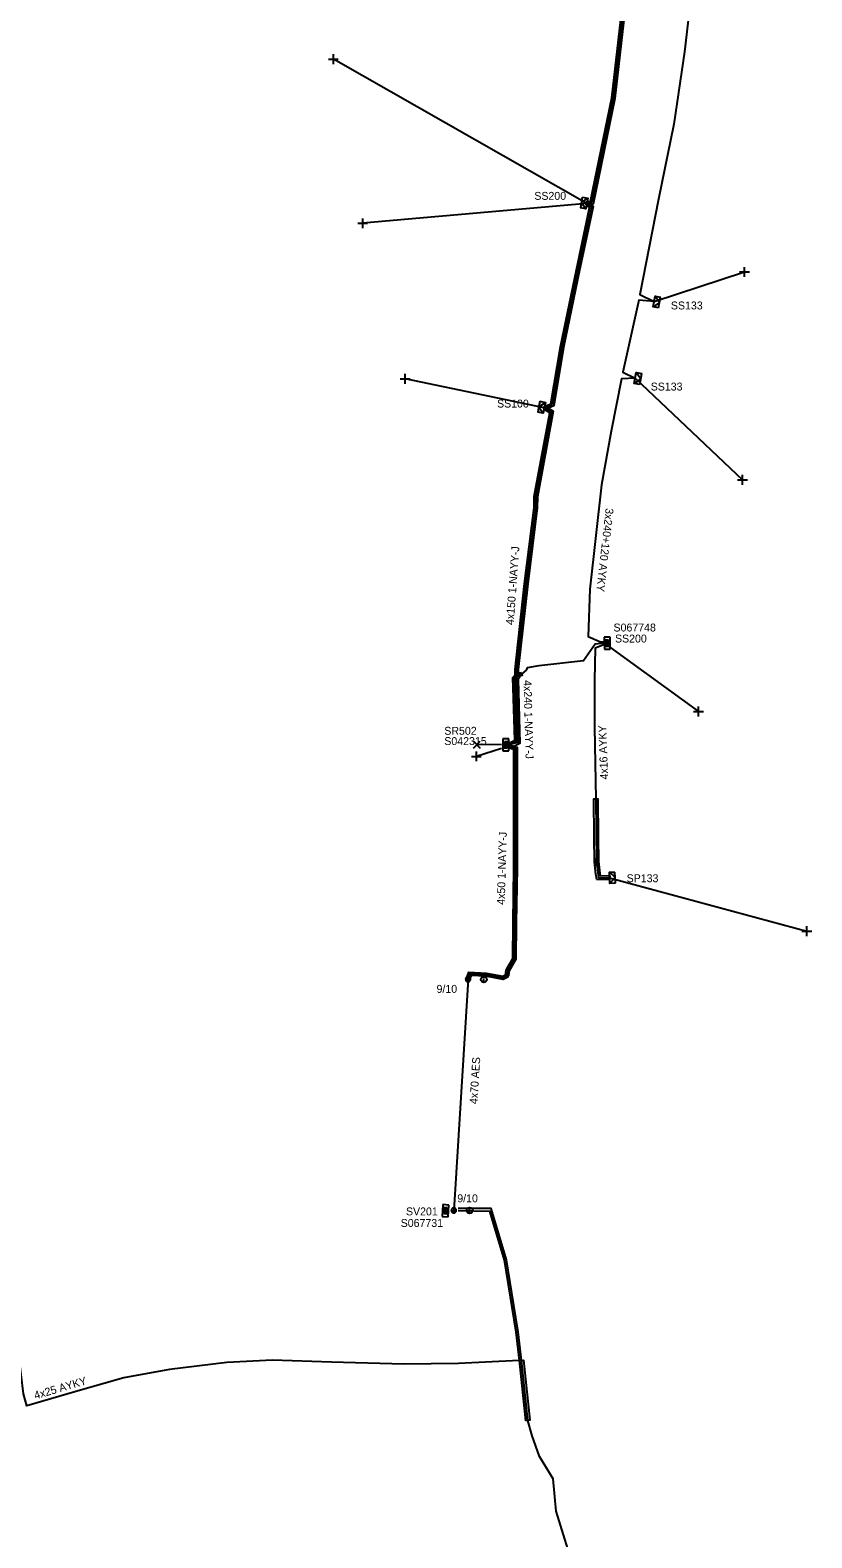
# Model space of a CAD drawing. Extents: x -748492 to -735633, y -1146251 to -1139940.
# Drawn here: x -736089.4 to -735990.6, y -1145586.5 to -1145396.1 of the extents above; entities that cross this region are included whole.
import ezdxf

# ---------------------------------------------------------------- set-up
doc = ezdxf.new("R2010")
doc.units = 0
for name, color, linetype in [('Vrstva 1', 7, 'Continuous'), ('Vrstva 10', 7, 'Continuous'), ('Vrstva 12', 7, 'Continuous'), ('Vrstva 13', 7, 'Continuous'), ('Vrstva 19', 7, 'Continuous'), ('Vrstva 2', 7, 'Continuous'), ('Vrstva 20', 7, 'Continuous'), ('Vrstva 28', 7, 'Continuous'), ('Vrstva 29', 7, 'Continuous'), ('Vrstva 30', 7, 'Continuous'), ('Vrstva 31', 7, 'Continuous'), ('Vrstva 33', 7, 'Continuous'), ('Vrstva 34', 7, 'Continuous'), ('Vrstva 36', 7, 'Continuous'), ('Vrstva 4', 7, 'Continuous'), ('Vrstva 5', 7, 'Continuous'), ('Vrstva 50', 7, 'Continuous'), ('Vrstva 51', 7, 'Continuous'), ('Vrstva 52', 7, 'Continuous'), ('Vrstva 54', 7, 'Continuous'), ('Vrstva 59', 7, 'Continuous'), ('Vrstva 6', 7, 'Continuous'), ('Vrstva 8', 7, 'Continuous'), ('Vrstva 9', 7, 'Continuous')]:
    doc.layers.add(name, color=color, linetype=linetype)

# ---------------------------------------------------------------- blocks, each defined once
blk = doc.blocks.new('NN440')
at = {"layer": 'Vrstva 2'}
for points in [[(0.63, 0), (0.63, 0.06), (0.62, 0.13), (0.6, 0.19), (0.58, 0.25), (0.55, 0.31), (0.51, 0.37), (0.47, 0.42), (0.42, 0.46), (0.37, 0.51), (0.32, 0.54), (0.26, 0.57), (0.2, 0.59), (0.13, 0.61), (0.07, 0.62), (0, 0.63), (-0.06, 0.62), (-0.13, 0.61), (-0.19, 0.59), (-0.26, 0.57), (-0.31, 0.54), (-0.37, 0.51), (-0.42, 0.46), (-0.47, 0.42), (-0.51, 0.37), (-0.54, 0.31), (-0.57, 0.25), (-0.6, 0.19), (-0.62, 0.13), (-0.63, 0.06), (-0.63, 0), (-0.63, -0.07), (-0.62, -0.14), (-0.6, -0.2), (-0.57, -0.26), (-0.54, -0.32), (-0.51, -0.37), (-0.47, -0.43), (-0.42, -0.47), (-0.37, -0.51), (-0.31, -0.55), (-0.26, -0.58), (-0.19, -0.6), (-0.13, -0.62), (-0.06, -0.63), (0, -0.63), (0.07, -0.63), (0.13, -0.62), (0.2, -0.6), (0.26, -0.58), (0.32, -0.55), (0.37, -0.51), (0.42, -0.47), (0.47, -0.43), (0.51, -0.37), (0.55, -0.32), (0.58, -0.26), (0.6, -0.2), (0.62, -0.14), (0.63, -0.07), (0.63, 0)], [(-0.63, 0), (0.63, 0)], [(-0.6, -0.18), (0.57, -0.18)], [(-0.51, -0.32), (0.5, -0.32)], [(-0.37, -0.47), (0.35, -0.47)]]:
    blk.add_lwpolyline(points, dxfattribs=at)
blk = doc.blocks.new('NN770')
at = {"layer": 'Vrstva 10'}
for p, q in [((0, 0.19), (0, 0.26)), ((0, -0.28), (0, 0.11))]:
    blk.add_line(p, q, dxfattribs=at)
blk.add_circle((0, -0.01), 0.375, dxfattribs=at)
blk = doc.blocks.new('NN870')
at = {"layer": 'Vrstva 4'}
for points in [[(0, -0.25), (0.5, 0), (0, 0.25), (-0.5, 0), (0, -0.25)], [(0.37, 0), (0, 0.19), (-0.36, 0), (0, -0.19), (0.37, 0)], [(0.24, 0), (0, 0.12), (-0.25, 0), (0, -0.12), (0.24, 0)], [(0.12, 0), (0, 0.06), (-0.13, 0), (0, -0.06), (0.12, 0)]]:
    blk.add_lwpolyline(points, dxfattribs=at)
blk = doc.blocks.new('NN800')
at = {"layer": 'Vrstva 1'}
for points in [[(-0.44, 0.44), (0.44, -0.44)], [(-0.44, -0.44), (0.44, 0.44)]]:
    blk.add_lwpolyline(points, dxfattribs=at)
blk = doc.blocks.new('NN620')
at = {"layer": 'Vrstva 8'}
for points in [[(0.75, 0), (-0.75, 0)], [(-0.75, 0), (-0.75, -0.75)], [(0.75, -0.75), (0.75, 0)], [(-0.75, -0.75), (0.75, -0.75)], [(0.37, -0.18), (-0.38, -0.18)], [(-0.38, -0.18), (-0.38, -0.56)], [(-0.38, -0.56), (0.37, -0.56)], [(0.32, -0.23), (-0.33, -0.23)], [(-0.33, -0.23), (-0.33, -0.51)], [(-0.33, -0.51), (0.32, -0.51)], [(0.27, -0.27), (-0.28, -0.27)], [(-0.28, -0.27), (-0.28, -0.46)], [(-0.28, -0.46), (0.27, -0.46)], [(0.23, -0.32), (-0.23, -0.32)], [(-0.23, -0.32), (-0.23, -0.42)], [(-0.23, -0.42), (0.23, -0.42)], [(-0.19, -0.37), (0.19, -0.37)], [(0.23, -0.42), (0.23, -0.32)], [(0.27, -0.46), (0.27, -0.27)], [(0.32, -0.51), (0.32, -0.23)], [(0.37, -0.56), (0.37, -0.18)]]:
    blk.add_lwpolyline(points, dxfattribs=at)
blk = doc.blocks.new('NN630')
at = {"layer": 'Vrstva 9'}
for points in [[(0, -0.7), (-0.7, 0)], [(-0.7, -0.7), (-0.7, 0), (0.7, 0), (0.7, -0.7)], [(-0.7, -0.7), (0.7, -0.7)], [(0, -0.7), (0.7, 0)]]:
    blk.add_lwpolyline(points, dxfattribs=at)

msp = doc.modelspace()

# ---------------------------------------------------------------- linework, layer by layer
at = {"layer": 'Vrstva 20'}
for points in [[(-736015.09, -1145385.83), (-736014.27, -1145386.45), (-736014.23, -1145393.69), (-736015.51, -1145404.72), (-736018.26, -1145418.06), (-736019.02, -1145418.18), (-736019.08, -1145417.78), (-736018.6, -1145417.7), (-736015.91, -1145404.66), (-736014.63, -1145393.67), (-736014.67, -1145386.65), (-736015.33, -1145386.15)], [(-736018.92, -1145417.82), (-736018.25, -1145418.37), (-736019.96, -1145426.42), (-736021.98, -1145436.18), (-736023.23, -1145443.55), (-736024.3, -1145443.98), (-736024.44, -1145443.6), (-736023.59, -1145443.27), (-736022.38, -1145436.1), (-736020.36, -1145426.34), (-736018.69, -1145418.53), (-736019.18, -1145418.13)], [(-736024.26, -1145443.62), (-736023.3, -1145444.22), (-736025.28, -1145455.03), (-736025.3, -1145456.41), (-736026.51, -1145466), (-736027.72, -1145476.84), (-736027.68, -1145477.52), (-736028.08, -1145477.54), (-736028.12, -1145476.83), (-736026.91, -1145465.96), (-736025.7, -1145456.39), (-736025.68, -1145454.99), (-736023.74, -1145444.42), (-736024.47, -1145443.96)], [(-736028.03, -1145477.4), (-736027.53, -1145477.81), (-736027.72, -1145478.05), (-736027.5, -1145486.16), (-736028.71, -1145486.75), (-736029, -1145486.17), (-736028.16, -1145485.76), (-736028.38, -1145477.83)], [(-736027.29, -1145477.19), (-736027.21, -1145477.58), (-736027.52, -1145477.65), (-736027.61, -1145477.26)], [(-736029.21, -1145514.7), (-736028.41, -1145513.31), (-736028.36, -1145508.84), (-736028.26, -1145501.86), (-736028.25, -1145486.94), (-736028.99, -1145486.72), (-736028.88, -1145486.33), (-736027.85, -1145486.64), (-736027.86, -1145501.86), (-736027.96, -1145508.84), (-736028.01, -1145513.42), (-736028.87, -1145514.9)], [(-736016.18, -1145503.39), (-736017.78, -1145503.34), (-736017.89, -1145502.67), (-736018.09, -1145501.12), (-736018.1, -1145497.94), (-736018.16, -1145493.15), (-736017.66, -1145493.15), (-736017.6, -1145497.94), (-736017.59, -1145501.09), (-736017.4, -1145502.6), (-736017.35, -1145502.86), (-736016.16, -1145502.89)], [(-736034.24, -1145515.83), (-736033.95, -1145515.04), (-736031.77, -1145515.17), (-736029.67, -1145515.55), (-736029.22, -1145515.33), (-736029.04, -1145515.69), (-736029.61, -1145515.97), (-736031.81, -1145515.57), (-736033.67, -1145515.46), (-736033.86, -1145515.97)], [(-736029.33, -1145515.48), (-736029.24, -1145514.77), (-736028.84, -1145514.82), (-736028.93, -1145515.53)], [(-736026.76, -1145571.69), (-736027.56, -1145564.08), (-736027.06, -1145564.03), (-736026.26, -1145571.63)]]:
    msp.add_lwpolyline(points, close=True, dxfattribs=at)
at = {"layer": 'Vrstva 5'}
for points in [[(-736014.43, -1145393.68), (-736015.71, -1145404.69), (-736018.43, -1145417.88), (-736019.05, -1145417.98), (-736018.47, -1145418.45), (-736020.16, -1145426.38), (-736022.18, -1145436.14), (-736023.41, -1145443.41), (-736024.42, -1145443.78), (-736023.52, -1145444.32), (-736025.48, -1145455.01), (-736025.5, -1145456.4), (-736026.71, -1145465.98), (-736027.92, -1145476.84), (-736027.88, -1145477.53), (-736028.18, -1145477.9), (-736027.96, -1145485.88), (-736028.92, -1145486.18)], [(-736005.97, -1145392.32), (-736006.69, -1145398.83), (-736008.07, -1145407.96), (-736010.01, -1145417.42), (-736012.35, -1145429.47), (-736010.55, -1145430.36), (-736012.46, -1145430.19), (-736014.48, -1145439.29), (-736012.93, -1145440.03), (-736014.65, -1145440.14), (-736015.98, -1145446.75), (-736017.18, -1145453.52), (-736018.66, -1145466.68), (-736018.87, -1145472.67), (-736017.31, -1145473.32), (-736016.84, -1145473.34)], [(-736016.85, -1145473.51), (-736017.98, -1145473.65), (-736019.46, -1145475.72), (-736025.13, -1145476.38), (-736026.59, -1145476.6), (-736026.71, -1145476.9)], [(-736026.71, -1145476.9), (-736027.25, -1145477.39), (-736027.56, -1145477.46), (-736027.98, -1145477.95), (-736027.77, -1145486.05), (-736028.91, -1145486.35)], [(-736028.93, -1145486.52), (-736028.05, -1145486.79), (-736028.06, -1145501.86), (-736028.16, -1145508.84), (-736028.21, -1145513.37), (-736029.04, -1145514.8), (-736029.13, -1145515.51), (-736029.64, -1145515.76), (-736031.79, -1145515.37), (-736033.81, -1145515.25), (-736034.05, -1145515.95)], [(-736003.14, -1145652.84), (-736002.58, -1145651.6), (-736003.13, -1145650.02), (-736003.94, -1145643.93), (-736004.36, -1145640.28), (-736006.72, -1145632.56), (-736009.92, -1145623.02), (-736012.35, -1145615.07), (-736013.07, -1145612.88), (-736017.45, -1145600.04), (-736020.54, -1145590.84), (-736022.91, -1145583.1), (-736023.32, -1145579.05), (-736025.01, -1145576.22), (-736025.94, -1145573.62), (-736026.51, -1145571.66), (-736027.31, -1145564.05), (-736027.71, -1145560.48), (-736028.25, -1145557.1), (-736029.19, -1145551.36), (-736031.12, -1145544.91), (-736033.71, -1145544.89), (-736035.31, -1145544.88)]]:
    msp.add_lwpolyline(points, dxfattribs=at)
at = {"layer": 'Vrstva 50'}
msp.add_lwpolyline([(-736034.05, -1145515.95), (-736035.85, -1145545.13)], dxfattribs=at)
at = {"layer": 'Vrstva 52'}
for points in [[(-736016.83, -1145473.66), (-736017.99, -1145474.12), (-736018.08, -1145478.2), (-736018.07, -1145484.14), (-736017.91, -1145493.15), (-736017.84, -1145501.1), (-736017.56, -1145503.1), (-736016.17, -1145503.14)], [(-736035.28, -1145545.14), (-736031.34, -1145545.21), (-736029.49, -1145551.42), (-736028.01, -1145560.52), (-736027.61, -1145564.09), (-736035.24, -1145564.48), (-736042.18, -1145564.55), (-736051.29, -1145564.29), (-736058.76, -1145564.03), (-736064.53, -1145564.35), (-736071.75, -1145565.22), (-736077.53, -1145566.27), (-736082.71, -1145567.73), (-736089.79, -1145569.81), (-736090.21, -1145568.29), (-736090.79, -1145563.41), (-736090.85, -1145561.19), (-736091.08, -1145561.22)]]:
    msp.add_lwpolyline(points, dxfattribs=at)
at = {"layer": 'Vrstva 59'}
for points in [[(-736019.05, -1145417.98), (-736051.06, -1145399.75)], [(-736019.05, -1145417.98), (-736047.36, -1145420.48)], [(-736010.55, -1145430.36), (-735999.13, -1145426.63)], [(-736024.42, -1145443.78), (-736042, -1145440.13)], [(-736012.93, -1145440.03), (-735999.38, -1145452.88)], [(-736016.16, -1145474.01), (-736004.94, -1145482.13)], [(-736029.81, -1145486.81), (-736033, -1145487.8)], [(-736029.82, -1145486.36), (-736032.94, -1145486.32)], [(-736016.17, -1145503.14), (-735991.25, -1145509.88)]]:
    msp.add_lwpolyline(points, dxfattribs=at)

# ---------------------------------------------------------------- block references
at = {"layer": 'Vrstva 13', "xscale": 0.4999999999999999, "yscale": 0.5, "rotation": 86.47011940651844}
msp.add_blockref('NN440', (-736034.05, -1145515.95), dxfattribs=at)
at = {"layer": 'Vrstva 13', "xscale": 0.5, "yscale": 0.5}
msp.add_blockref('NN440', (-736035.85, -1145545.13), dxfattribs=at)
at = {"layer": 'Vrstva 19', "rotation": 90}
msp.add_blockref('NN870', (-736017.84, -1145501.1), dxfattribs=at)
at = {"layer": 'Vrstva 28'}
for p, rotation in [((-736016.85, -1145473.51), 91.4192000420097), ((-736028.91, -1145486.35), -90.72066386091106), ((-736036.53, -1145545.2), -93.5298805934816)]:
    msp.add_blockref('NN620', p, dxfattribs=dict(at, rotation=rotation))
at = {"layer": 'Vrstva 31'}
for p, rotation in [((-736019.05, -1145417.98), -100.10092784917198), ((-736010.55, -1145430.36), 79.54862506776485), ((-736012.93, -1145440.03), 79.61674447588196), ((-736024.42, -1145443.78), -101.03314444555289), ((-736016.17, -1145503.14), 92.10994170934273)]:
    msp.add_blockref('NN630', p, dxfattribs=dict(at, rotation=rotation))
at = {"layer": 'Vrstva 34'}
for p, rotation in [((-736051.06, -1145399.75), 45), ((-736047.36, -1145420.48), 45), ((-735999.13, -1145426.63), 45), ((-736042, -1145440.13), 45), ((-735999.38, -1145452.88), 45), ((-736004.94, -1145482.13), 44.99999995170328), ((-736033, -1145487.8), 45), ((-735991.25, -1145509.88), 45)]:
    msp.add_blockref('NN800', p, dxfattribs=dict(at, rotation=rotation))
msp.add_blockref('NN800', (-736032.94, -1145486.32), dxfattribs=at)
at = {"layer": 'Vrstva 36'}
for p in [(-736032.05, -1145515.95), (-736033.85, -1145545.13)]:
    msp.add_blockref('NN770', p, dxfattribs=at)

# ---------------------------------------------------------------- texts
at = {"layer": 'Vrstva 12'}
for p in [(-736038.03, -1145517.66), (-736035.41, -1145544.11)]:
    msp.add_text('9/10', height=1, dxfattribs=at).set_placement(p)
at = {"layer": 'Vrstva 29'}
for s, p in [('S067748', (-736015.68, -1145472.03)), ('S042315', (-736037.05, -1145486.37)), ('S067731', (-736042.56, -1145547.22))]:
    msp.add_text(s, height=1, dxfattribs=at).set_placement(p)
at = {"layer": 'Vrstva 30'}
for s, p in [('SS200', (-736015.49, -1145473.42)), ('SR502', (-736037.05, -1145485.07)), ('SV201', (-736041.89, -1145545.76))]:
    msp.add_text(s, height=1, dxfattribs=at).set_placement(p)
at = {"layer": 'Vrstva 33'}
for s, p in [('SS200', (-736025.68, -1145417.52)), ('SS133', (-736008.43, -1145431.36)), ('SS133', (-736010.98, -1145441.6)), ('SS100', (-736030.39, -1145443.75)), ('SP133', (-736014.02, -1145503.69))]:
    msp.add_text(s, height=1, dxfattribs=at).set_placement(p)
at = {"layer": 'Vrstva 51'}
msp.add_text('4x70 AES', height=1, rotation=86.47, dxfattribs=at).set_placement((-736032.87, -1145531.73))
at = {"layer": 'Vrstva 54'}
for s, rotation, p in [('4x16 AYKY', 91.984, (-736016.36, -1145490.7)), ('4x25 AYKY', 16.372, (-736088.7, -1145569))]:
    msp.add_text(s, height=1, rotation=rotation, dxfattribs=at).set_placement(p)
at = {"layer": 'Vrstva 6'}
for s, rotation, p in [('3x240+120 AYKY', 263.584, (-736016.66, -1145456.42)), ('4x150 1-NAYY-J', 85.77, (-736028.29, -1145471.24)), ('4x240 1-NAYY-J', 271.511, (-736027.04, -1145478.18)), ('4x50 1-NAYY-J', 88.309, (-736029.42, -1145506.55))]:
    msp.add_text(s, height=1, rotation=rotation, dxfattribs=at).set_placement(p)

doc.saveas('drawing.dxf')
